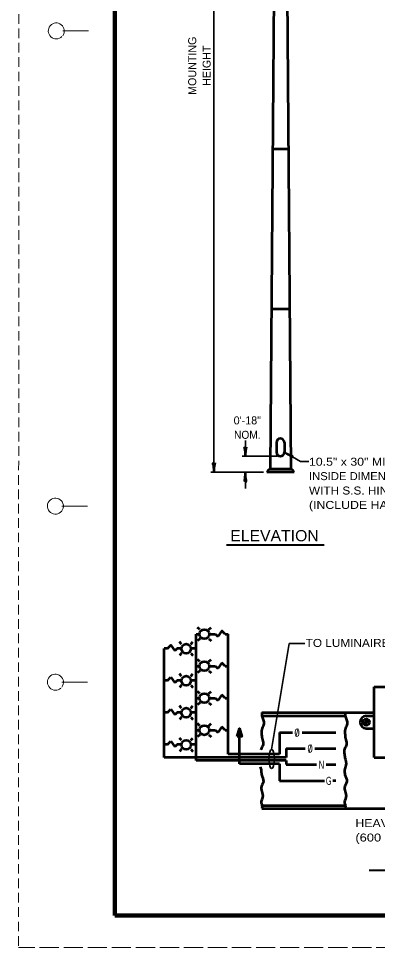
# Model space of a CAD drawing. Extents: x -1 to 679, y 0 to 440.
# Drawn here: x -1.5 to 110.4, y -0.4 to 289.7 of the extents above; entities that cross this region are included whole.
import ezdxf
from ezdxf.enums import TextEntityAlignment as Align

# ---------------------------------------------------------------- set-up
doc = ezdxf.new("R2010")
doc.units = 0
doc.linetypes.add('LONG_DASHED', pattern=[7.5, 6, -1.5])
doc.linetypes.add('MEDIUM_DASHED', pattern=[4.5, 3, -1.5])
doc.layers.add('1', color=7, linetype='Continuous', lineweight=35)
doc.layers.add('61', color=7, linetype='Continuous', lineweight=35)

msp = doc.modelspace()

# ---------------------------------------------------------------- linework, layer by layer
at = {"layer": '1', "linetype": 'MEDIUM_DASHED', "lineweight": 13}
msp.add_line((-1.425, 439.645), (-1.485, -0.395), dxfattribs=at)
at = {"layer": '1'}
for p, q in [((59.446, 148.054), (59.446, 401.804)), ((69.252, 153.001), (69.252, 158.001)), ((81.446, 154.304), (86.495, 151.389)), ((79.196, 153.054), (68.252, 153.054)), ((86.495, 151.389), (89.043, 151.389)), ((74.946, 148.054), (58.446, 148.054)), ((69.252, 148.001), (69.252, 143.001)), ((77.458, 61.45), (82.907, 94.504)), ((87.765, 94.504), (82.907, 94.504))]:
    msp.add_line(p, q, dxfattribs=at)
at = {"layer": '1', "lineweight": 53}
for p, q in [((78.946, 399.063), (76.946, 149.054)), ((81.446, 399.056), (83.446, 149.054)), ((77.746, 249.054), (82.646, 249.054)), ((77.346, 199.054), (83.046, 199.054)), ((78.946, 157.304), (78.946, 154.304)), ((81.446, 157.304), (81.446, 154.304)), ((84.446, 148.054), (75.946, 148.054)), ((76.946, 149.054), (83.446, 149.054)), ((55.025, 98.873), (54.318, 99.58)), ((57.854, 98.873), (58.561, 99.58)), ((53.94, 57.959), (53.94, 97.459)), ((53.94, 97.459), (54.94, 97.459)), ((55.025, 96.044), (54.318, 95.337)), ((57.854, 96.044), (58.561, 95.337)), ((57.94, 97.459), (59.94, 97.459)), ((59.94, 97.459), (60.647, 96.752)), ((62.94, 97.459), (63.94, 97.459)), ((63.94, 59.959), (63.94, 97.459)), ((43.94, 58.959), (43.94, 92.959)), ((44.94, 92.959), (43.94, 92.959)), ((47.94, 92.959), (47.233, 92.252)), ((49.285, 92.959), (47.94, 92.959)), ((49.369, 94.31), (48.662, 95.018)), ((52.198, 94.31), (52.905, 95.018)), ((53.94, 92.959), (52.282, 92.959)), ((49.369, 91.482), (48.662, 90.775)), ((52.198, 91.482), (52.905, 90.775)), ((53.94, 87.459), (54.94, 87.459)), ((55.025, 88.873), (54.318, 89.58)), ((57.854, 88.873), (58.561, 89.58)), ((57.94, 87.459), (59.94, 87.459)), ((59.94, 87.459), (60.647, 86.752)), ((61.879, 88.519), (60.647, 86.752)), ((62.94, 87.459), (61.879, 88.519)), ((62.94, 87.459), (63.94, 87.459)), ((49.369, 84.31), (48.662, 85.018)), ((52.198, 84.31), (52.905, 85.018)), ((55.025, 86.044), (54.318, 85.337)), ((57.854, 86.044), (58.561, 85.337)), ((44.94, 82.959), (43.94, 82.959)), ((44.94, 82.959), (46, 84.019)), ((46, 84.019), (47.233, 82.252)), ((47.94, 82.959), (47.233, 82.252)), ((49.285, 82.959), (47.94, 82.959)), ((49.369, 81.482), (48.662, 80.775)), ((52.198, 81.482), (52.905, 80.775)), ((53.94, 82.959), (52.282, 82.959)), ((55.025, 78.873), (54.318, 79.58)), ((57.854, 78.873), (58.561, 79.58)), ((61.879, 78.519), (60.647, 76.752)), ((62.94, 77.459), (61.879, 78.519)), ((109.44, 58.959), (109.44, 80.959)), ((109.44, 80.959), (126.94, 80.959)), ((53.94, 77.459), (54.94, 77.459)), ((55.025, 76.044), (54.318, 75.337)), ((57.854, 76.044), (58.561, 75.337)), ((57.94, 77.459), (59.94, 77.459)), ((59.94, 77.459), (60.647, 76.752)), ((62.94, 77.459), (63.94, 77.459)), ((44.94, 72.959), (43.94, 72.959)), ((44.94, 72.959), (46, 74.019)), ((46, 74.019), (47.233, 72.252)), ((47.94, 72.959), (47.233, 72.252)), ((49.285, 72.959), (47.94, 72.959)), ((49.369, 74.31), (48.662, 75.018)), ((52.198, 74.31), (52.905, 75.018)), ((53.94, 72.959), (52.282, 72.959)), ((49.369, 71.482), (48.662, 70.775)), ((52.198, 71.482), (52.905, 70.775)), ((74.44, 71.959), (100.44, 71.959)), ((106.15, 69.346), (107.553, 70.749)), ((106.326, 69.169), (107.73, 70.572)), ((106.94, 71.959), (109.44, 71.959)), ((53.94, 67.459), (54.94, 67.459)), ((55.025, 68.873), (54.318, 69.58)), ((57.854, 68.873), (58.561, 69.58)), ((57.94, 67.459), (59.94, 67.459)), ((59.94, 67.459), (60.647, 66.752)), ((61.879, 68.519), (60.647, 66.752)), ((62.94, 67.459), (61.879, 68.519)), ((62.94, 67.459), (63.94, 67.459)), ((67.44, 56.959), (67.44, 67.324)), ((106.94, 67.959), (109.44, 67.959)), ((44.94, 62.959), (46, 64.019)), ((46, 64.019), (47.233, 62.252)), ((49.369, 64.311), (48.662, 65.018)), ((52.198, 64.311), (52.905, 65.018)), ((55.025, 66.044), (54.318, 65.337)), ((57.854, 66.044), (58.561, 65.337)), ((79.94, 66.709), (79.94, 59.959)), ((79.94, 66.709), (83.94, 66.709)), ((86.94, 66.709), (97.493, 66.709)), ((44.94, 62.959), (43.94, 62.959)), ((47.94, 62.959), (47.233, 62.252)), ((49.285, 62.959), (47.94, 62.959)), ((49.369, 61.482), (48.662, 60.775)), ((52.198, 61.482), (52.905, 60.775)), ((53.94, 62.959), (52.282, 62.959)), ((81.94, 61.709), (81.94, 58.959)), ((81.94, 61.709), (87.94, 61.709)), ((90.94, 61.709), (97.493, 61.709)), ((81.94, 58.959), (43.94, 58.959)), ((79.94, 59.959), (63.94, 59.959)), ((109.44, 58.959), (126.94, 58.959)), ((81.94, 57.959), (53.94, 57.959)), ((79.94, 56.959), (67.44, 56.959)), ((79.94, 56.959), (79.94, 51.694)), ((81.94, 57.959), (81.94, 56.725)), ((81.94, 56.725), (91.44, 56.725)), ((94.44, 56.725), (97.493, 56.725)), ((79.94, 51.694), (93.94, 51.694)), ((97.493, 51.694), (96.493, 51.694)), ((74.44, 43.959), (100.44, 43.959)), ((74.44, 42.959), (100.44, 42.959))]:
    msp.add_line(p, q, dxfattribs=at)
at = {"layer": '1', "lineweight": 40}
for p, q in [((63.338, 125.369), (93.827, 125.369)), ((107.891, 23.773), (207.154, 23.773))]:
    msp.add_line(p, q, dxfattribs=at)
at = {"layer": '1', "lineweight": 53}
for points in [[(62.94, 97.459), (61.879, 98.519), (60.647, 96.752)], [(44.94, 92.959), (46, 94.019), (47.233, 92.252)], [(74.44, 72.959), (100.44, 72.959), (109.44, 72.959)], [(100.44, 42.959), (135.94, 42.959), (223.44, 42.959)]]:
    msp.add_lwpolyline(points, dxfattribs=at)
msp.add_lwpolyline([(66.69, 65.459), (67.44, 67.959), (68.19, 65.459)], close=True, dxfattribs=at)
for centre, radius in [((56.44, 97.459), 1.5), ((50.784, 92.896), 1.5), ((56.44, 87.459), 1.5), ((50.784, 82.896), 1.5), ((56.44, 77.459), 1.5), ((50.784, 72.896), 1.5), ((106.94, 69.959), 1), ((56.44, 67.459), 1.5), ((50.784, 62.896), 1.5)]:
    msp.add_circle(centre, radius, dxfattribs=at)
for centre, radius, start, end in [((80.196, 157.304), 1.25, 0, 180), ((80.196, 154.304), 1.25, 180, 0), ((77.76, 147.24), 1.988, 114.16843, 155.83157), ((82.632, 147.24), 1.988, 24.16843, 65.83157), ((107.084, 69.959), 2.005, 94.11744, 265.88257)]:
    msp.add_arc(centre, radius, start, end, dxfattribs=at)
at = {"layer": '1', "lineweight": 40}
for centre, major_axis, ratio, start_param, end_param in [((68.975, 154.092), (0.156, -1.786), 0.122415, 0.8963533, 3.1415927), ((68.975, 154.092), (0.156, -1.786), 0.122415, 0.8963533, 3.1415927), ((69.463, 154.121), (-0.176, -1.756), 0.07063, 3.1407148, 5.41811), ((69.463, 154.121), (-0.176, -1.756), 0.07063, 3.1407148, 5.41811), ((82.31, 153.56), (-1.433, 1.03), 0.07063, 3.1407148, 5.41811), ((82.529, 153.997), (-1.625, 0.758), 0.122415, 0.8963533, 3.1415927), ((59.169, 149.145), (0.156, -1.786), 0.122415, 0.8963533, 3.1415927), ((59.169, 149.145), (0.156, -1.786), 0.122415, 0.8963533, 3.1415927), ((59.657, 149.174), (-0.176, -1.756), 0.07063, 3.1407148, 5.41811), ((59.657, 149.174), (-0.176, -1.756), 0.07063, 3.1407148, 5.41811), ((69.04, 146.88), (0.176, 1.756), 0.07063, 3.1407148, 5.41811), ((69.04, 146.88), (0.176, 1.756), 0.07063, 3.1407148, 5.41811), ((69.528, 146.91), (-0.156, 1.786), 0.122415, 0.8963533, 3.1415927), ((69.528, 146.91), (-0.156, 1.786), 0.122415, 0.8963533, 3.1415927)]:
    msp.add_ellipse(centre, major_axis=major_axis, ratio=ratio, start_param=start_param, end_param=end_param, dxfattribs=at)
at = {"layer": '1'}
msp.add_ellipse((77.458, 58.45), major_axis=(0, -3), ratio=0.286071, dxfattribs=at)
at = {"layer": '1', "lineweight": 53}
for points in [[(74.44, 72.978), (74.44, 71.978), (75.054, 69.457), (74.452, 68.073), (74.332, 66.449), (74.452, 64.884), (74.693, 64.042), (74.693, 62.718), (74.152, 61.575), (74.111, 61.325)], [(100.44, 72.959), (100.44, 71.959), (101.054, 69.437), (100.452, 68.054), (100.332, 66.429), (100.452, 64.865), (100.693, 64.022), (100.693, 62.699), (100.152, 61.555), (100.091, 60.292), (100.332, 58.848), (100.633, 56.501), (100.212, 54.997), (100.332, 53.553), (100.873, 51.387), (100.212, 49.462), (100.513, 47.897), (100.513, 46.032), (100.152, 44.949), (100.44, 43.959), (100.44, 42.959)], [(74.258, 54.138), (74.297, 54.808), (73.961, 56.006)], [(74.257, 54.151), (74.332, 53.573), (74.873, 51.407), (74.212, 49.481), (74.513, 47.917), (74.513, 46.051), (74.152, 44.968), (74.44, 43.978), (74.44, 42.978)]]:
    msp.add_spline(points, degree=3, dxfattribs=at)
at = {"layer": '61', "lineweight": 13}
for p, q in [((12.275, 285.885), (20.275, 285.885)), ((11.995, 137.465), (19.995, 137.465)), ((12.015, 82.445), (19.995, 82.445))]:
    msp.add_line(p, q, dxfattribs=at)
at = {"layer": '61', "lineweight": 158}
msp.add_line((667.635, 9.605), (28.575, 9.625), dxfattribs=at)
at = {"layer": '61', "linetype": 'LONG_DASHED', "lineweight": 13}
msp.add_line((678.575, -0.375), (-1.485, -0.395), dxfattribs=at)
at = {"layer": '61', "lineweight": 158}
msp.add_lwpolyline([(667.615, 429.645), (28.575, 429.645), (28.575, 9.625)], dxfattribs=at)
at = {"layer": '61', "lineweight": 13}
for centre, start, end in [((10.273, 285.887), 323.13009, 315.37577), ((9.993, 137.447), 322.67175, 321.71615), ((9.993, 82.447), 323.13009, 312.31439)]:
    msp.add_arc(centre, 2.5, start, end, dxfattribs=at)

# ---------------------------------------------------------------- texts
at = {"layer": '1'}
for s, p in [('MOUNTING', (53.925, 275.011)), ('HEIGHT', (58.425, 275.011))]:
    msp.add_text(s, height=2.5, rotation=90, dxfattribs=at).set_placement(p, align=Align.CENTER)
for s, p in [('0\'-18"', (69.866, 162.981)), ('/', (85.374, 65.391)), ('/', (89.43, 60.37))]:
    msp.add_text(s, height=2.5, dxfattribs=at).set_placement(p, align=Align.CENTER)
for s, height, width, p in [('NOM.', 2.5, 0.95, (69.867, 158.481)), ('ELEVATION', 3.5, 1.05, (78.344, 126.473)), ('TO LUMINAIRES', 2.5, 1.1, (102.376, 93.468)), ('0', 2.5, 0.9, (85.375, 65.434)), ('0', 2.5, 0.9, (89.458, 60.454)), ('N', 2.5, 0.7, (92.978, 55.427)), ('G', 2.5, 0.7, (95.277, 50.396))]:
    msp.add_text(s, height=height, dxfattribs=dict(at, width=width)).set_placement(p, align=Align.CENTER)
for s, width, p in [('10.5" x 30" MIN.', 1.15, (89.095, 150.075)), ('INSIDE DIMENSIONS', 1.05, (89.095, 145.575)), ('WITH S.S. HINGES', 1.1, (89.095, 141.075)), ('(INCLUDE HASP WITH LOCK)', 1.15, (89.095, 136.575)), ('HEAVY DUTY TERMINAL', 1.15, (103.579, 37.176)), ('(600 V) BOARD', 1.2, (103.579, 32.676))]:
    msp.add_text(s, height=2.5, dxfattribs=dict(at, width=width)).set_placement(p)

doc.saveas('drawing.dxf')
